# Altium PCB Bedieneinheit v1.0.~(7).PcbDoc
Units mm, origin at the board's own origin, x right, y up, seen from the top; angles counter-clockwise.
Board outline 100 x 75 mm, 2 copper layers (Top Layer, Bottom Layer); 71 components, 61 nets, 264 pads, 32 vias.
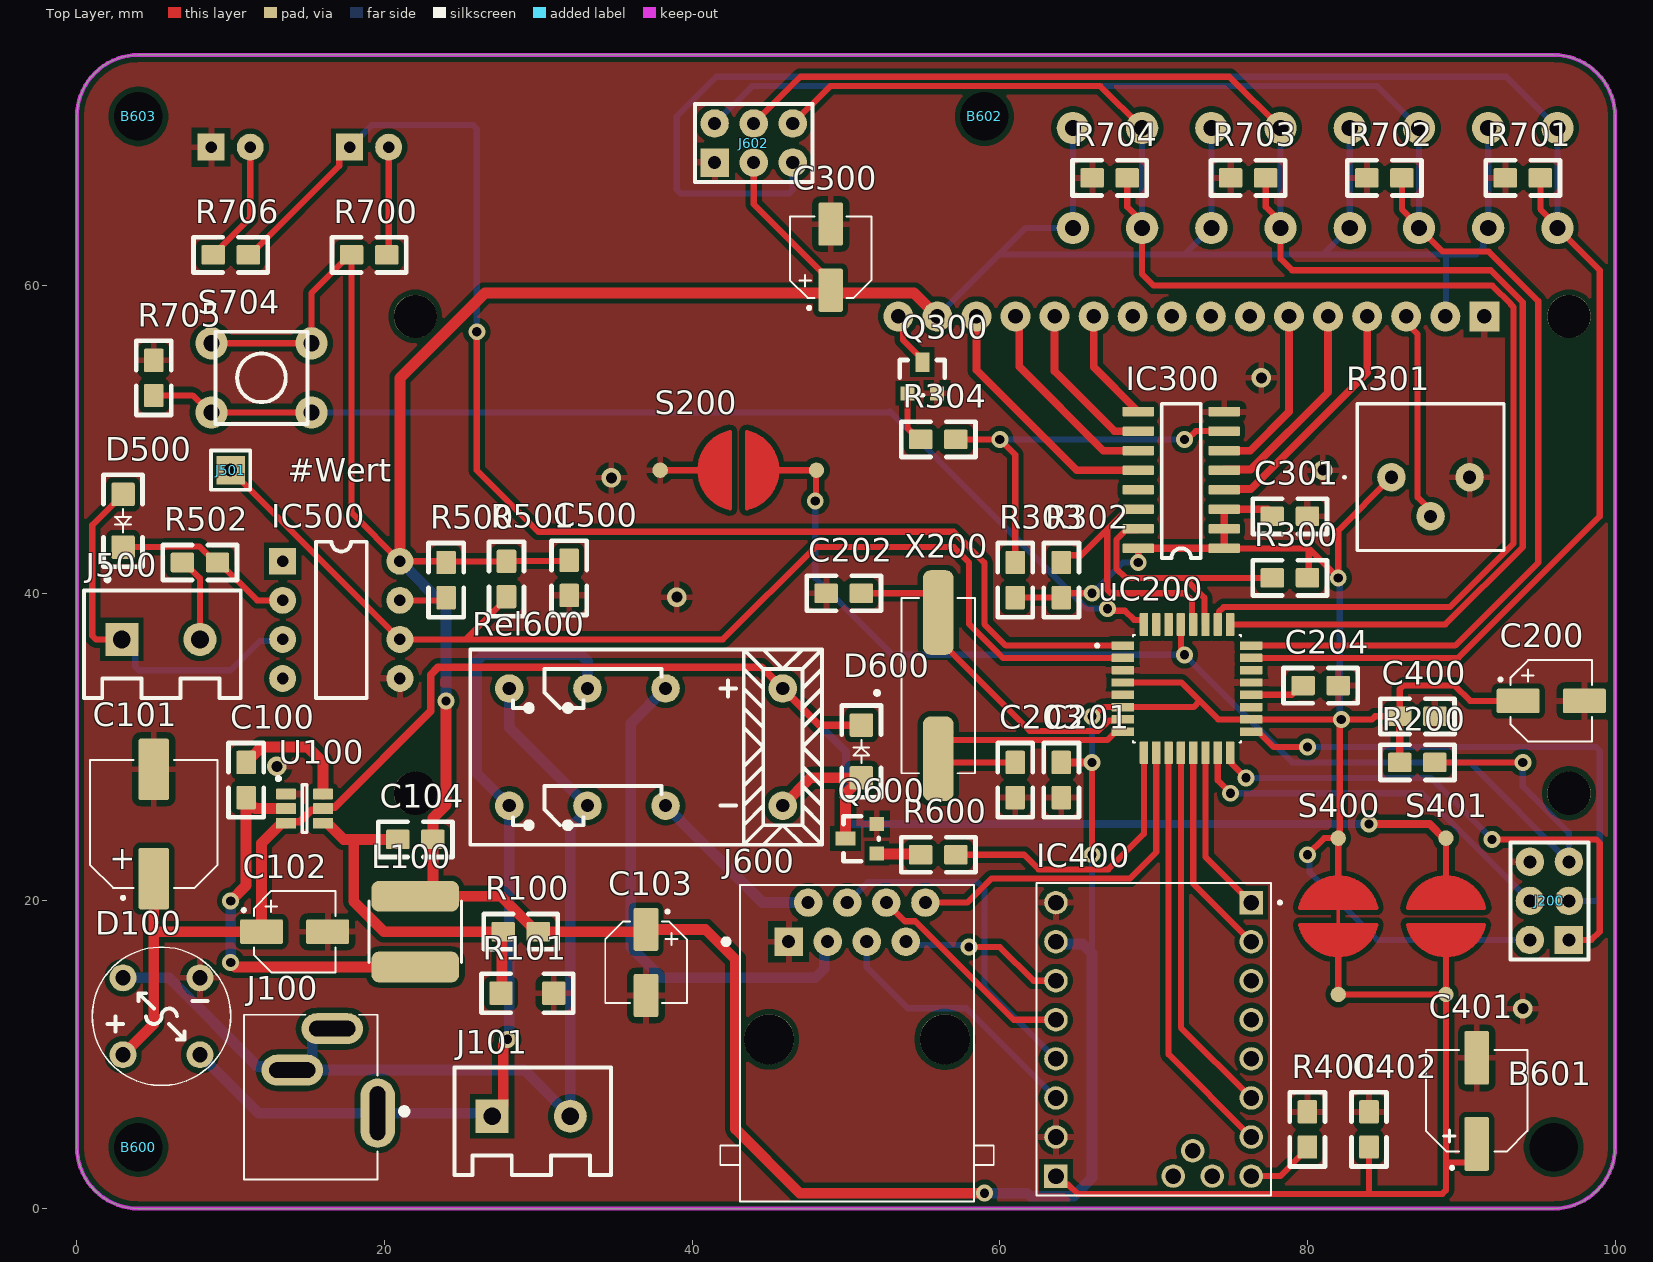
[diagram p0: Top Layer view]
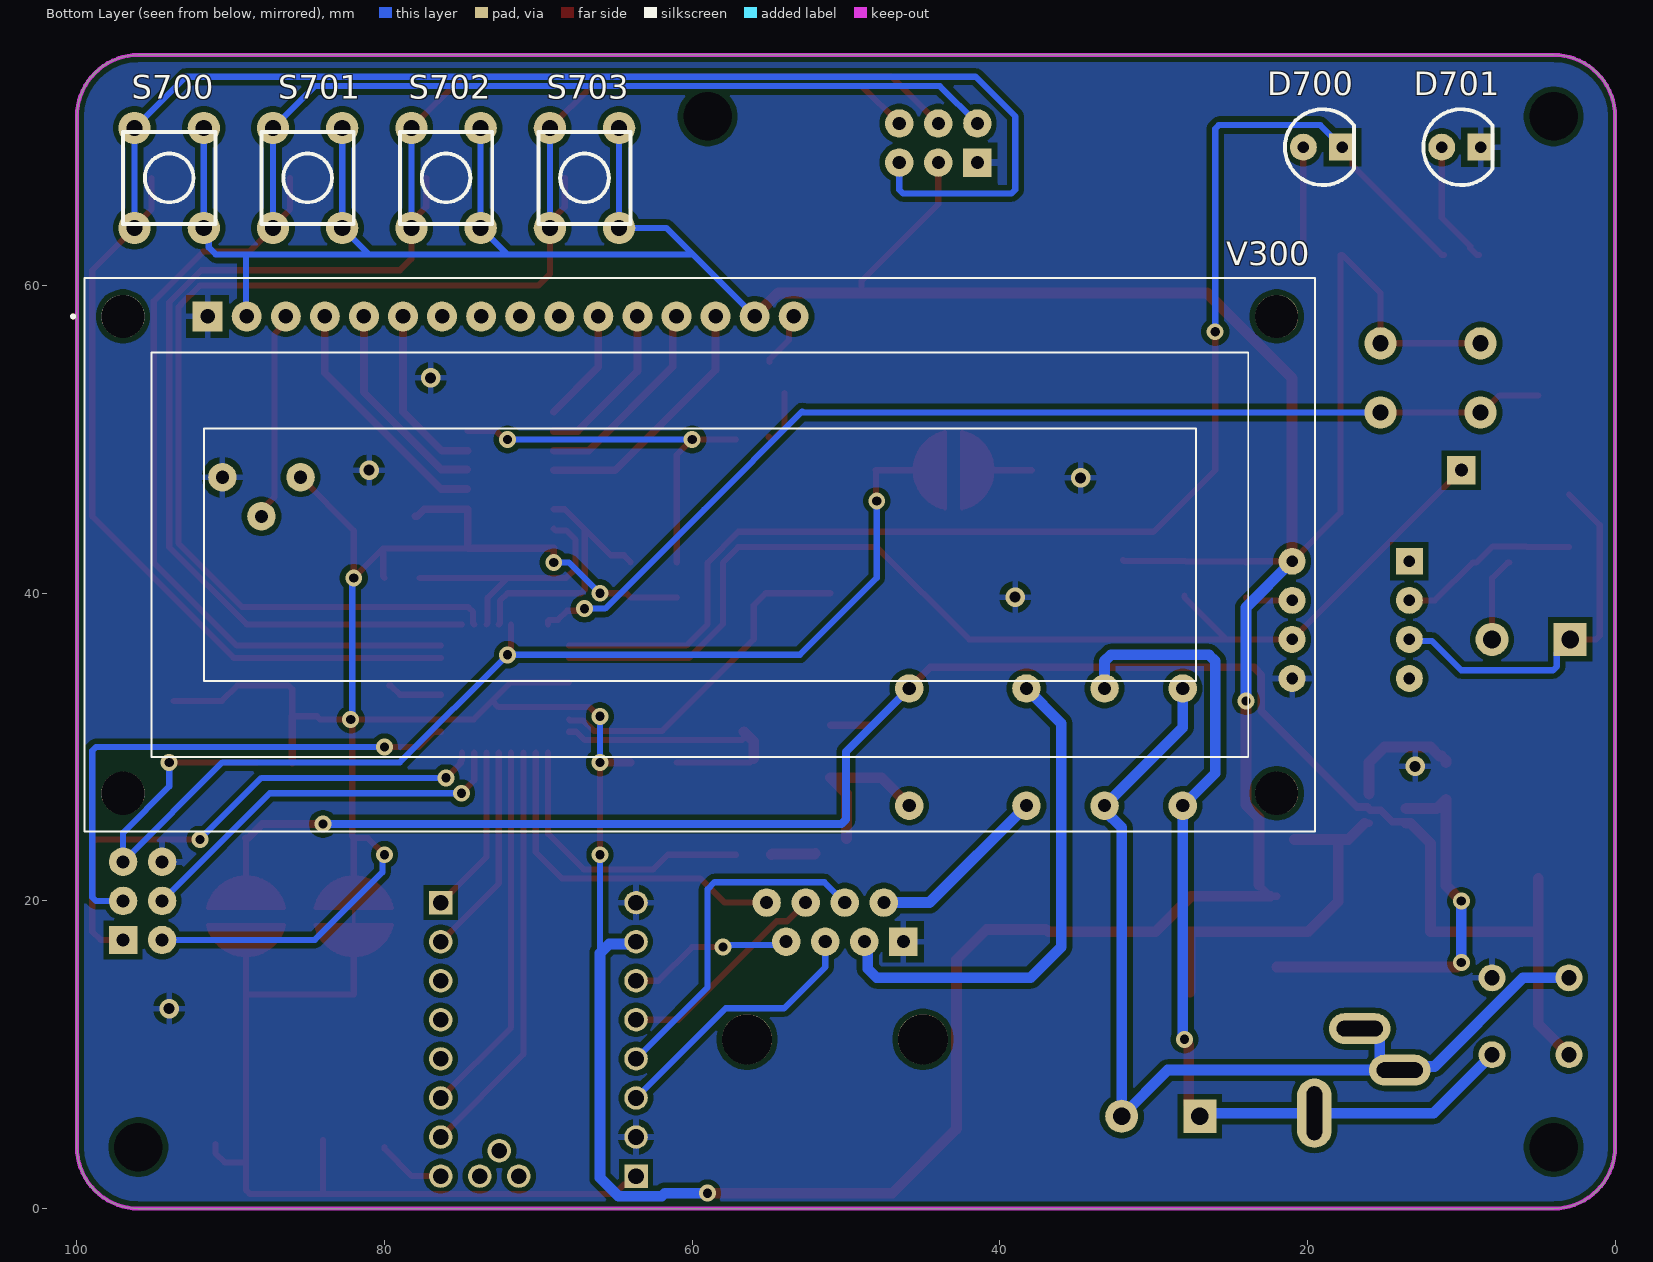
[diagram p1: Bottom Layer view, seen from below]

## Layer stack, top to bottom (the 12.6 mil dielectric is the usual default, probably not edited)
Top Solder: solder mask 0.0102, Solder Resist, Dk 3.5
Top Layer: signal copper 0.0356
Dielectric 1: dielectric 0.32, FR-4, Dk 4.8
Bottom Layer: signal copper 0.0356
Bottom Solder: solder mask 0.0102, Solder Resist, Dk 3.5

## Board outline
0,4 0,71 cw(c4,71) 4,75 96,75 cw(c96,71) 100,71 100,4 cw(c96,4) 96,0 4,0 cw(c4,4)

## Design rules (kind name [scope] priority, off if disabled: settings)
Clearance [All] p1: gap=0.35 ignorepadtopadclearanceinfootprint=FALSE except(0.2: Arc-Arc Arc-Track Arc-SMDPad Arc-THPad Arc-Via Arc-Text Arc-Hole Track-Track Track-SMDPad Track-THPad Track-Via Track-Text Track-Hole SMDPad-SMDPad SMDPad-THPad SMDPad-Via SMDPad-Text SMDPad-Hole THPad-THPad THPad-Via THPad-Text THPad-Hole Via-Via Via-Text Via-Hole Text-Text Text-Hole)
HoleSize [All] p1: absolutevalues=TRUE maxlimit=4 minlimit=0.4 maxpercent=80.000 minpercent=20.000
MinimumAnnularRing [All] p1: minimumring=0.2
MinimumSolderMaskSliver [All] p1: minsoldermaskwidth=0
PolygonConnect [All] p1: connectstyle=Relief reliefconductorwidth=0.4 reliefentries=4 polygonreliefangle="90 Angle" airgapwidth=0.4
RoutingVias [All] p1: holewidth=0.6 width=1.1 viastyle="Through Hole" minholewidth=0.5 minwidth=1 maxholewidth=1 maxwidth=2
SilkToSilkClearance [All] p1: silktosilkclearance=0
SilkToSolderMaskClearance [IsPad] p1: minsilkscreentomaskgap=0 clearancetoexposedcopper=TRUE
SolderMaskExpansion [All] p1: expansion=0.102 istentingtop=FALSE
Width [All] p1: maxlimit=6 minlimit=0.3 preferedwidth=0.5
26 further rules are at their usual default settings.

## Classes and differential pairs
component class "7.0 Bedieneinheit": D700 D701 R700 R701 R702 R703 R704 R705 R706 S700 S701 S702 S703 S704
component class "6.0 Relais and Connector": B600 B601 B602 B603 D600 J600 J602 Q600 R600 Rel600
component class "5.0 Demodulation": C500 D500 IC500 J500 J501 R500 R501 R502
component class "4.0 Steppermotor & Peripheral": C400 C401 C402 IC400 R400 S400 S401
component class "3.0 Display": C300 C301 IC300 Q300 R300 R301 R302 R303 R304 V300
component class "2.0 Microcontroller": C200 C201 C202 C203 C204 J200 R200 S200 uC200 X200
component class "1.0 PSU": C100 C101 C102 C103 C104 D100 J100 J101 L100 R100 R101 U100

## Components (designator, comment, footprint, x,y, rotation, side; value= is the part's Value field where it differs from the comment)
B600 "Schraube" B_Schraube-M3 4,4 r0 top
B601 "Schraube" B_Schraube-M3 96,4 r0 top
B602 "Schraube" B_Schraube-M3 59,71 r0 top
B603 "Schraube" B_Schraube-M3 4,71 r0 top
C100 "100nf" C_SMD_0805 11,27.857 r270 top
C101 "470uf" C_SMD_F-TYP 5,25 r90 top
C102 "10uf" C_SMD_C-TYP 14.15,18 r0 top
C103 "22uf" C_SMD_C-TYP 37,16 r270 top
C104 "22pf" C_SMD_0805 22,24 r180 top
C200 "10uf" C_SMD_C-TYP 95.85,33 r0 top
C201 "100nf" C_SMD_0805 64,27.857 r270 top
C202 "22pf" C_SMD_0805 49.857,40 r180 top
C203 "22pf" C_SMD_0805 61,27.857 r270 top
C204 "100nf" C_SMD_0805 80.857,34 r0 top
C300 "10uf" C_SMD_C-TYP 49,61.85 r90 top
C301 "100nf" C_SMD_0805 78.857,45 r0 top
C400 "100nf" C_SMD_0805 87.143,32 r0 top
C401 "100uf" C_SMD_D-TYP 91,7 r90 top
C402 "100nf" C_SMD_0805 84,5.143 r90 top
C500 "1uf" C_SMD_0805 32,41 r270 top
D100 "B500R" D_THT_FBR-R 3,10 r0 top
D500 "FDLL4148" D_SMD_1206 3,44.715 r270 top
D600 "FDLL4148" D_SMD_1206 51,29.714 r90 top
D700 "LED-YELLOW" D_THT_LED-5 19,69 r180 bottom
D701 "LED-YELLOW" D_THT_LED-5 10,69 r180 bottom
IC300 "PCF8574" SO-16 74.588,42.92 r180 top
IC400 "TMC2208" IC_TMC2208 70,11 r0 top
IC500 "6N137" DIP-8 13.38,42.08 r0 top
J100 "DC-Buchse" J_THT_CUI_PJ-006A 19.55,6.2 r270 top
J101 "VIN" "J_THT_Printklemme 2x" 29.54,6 r0 top
J200 "PROG" J_2x3 95.73,20 r90 top
J500 "DCC" "J_THT_Printklemme 2x" 5.46,37 r0 top
J501 "#Wert" SIP-1 10,49.27 r90 top
J600 "RJ45 Buchse" J_TE-RJ45-8L-B 50.715,11 r0 top
J602 "CON 2x3" J_2x3 44,69.27 r0 top
L100 "6,8uH" L_SMD_BWVS00606045 22,18 r180 top
Q300 "BC847B" SOT-23 54,53 r0 top
Q600 "BC848B" SOT-23 52,23.095 r90 top
R100 "40k2" R_SMD_0805 28.857,18 r0 top
R101 "7k68" R_SMD_1206 29.285,14 r180 top
R200 "10k" R_SMD_0805 87.143,29 r0 top
R300 "10k" R_SMD_0805 78.857,41 r0 top
R301 "10k" R_THT_POT-TP-.2/.1 85.46,47.54 r0 top
R302 "10k" R_SMD_0805 64,40.857 r270 top
R303 "10k" R_SMD_0805 61,40.857 r270 top
R304 "1k" R_SMD_0805 56,50 r180 top
R400 "0R0" R_SMD_0805 80,5.143 r270 top
R500 "10k" R_SMD_0805 24,40.857 r90 top
R501 "10k" R_SMD_0805 27.929,40.929 r90 top
R502 "1k" R_SMD_0805 8,42 r0 top
R600 "1k" R_SMD_0805 56,23 r180 top
R700 "470R" R_SMD_0805 19,62 r180 top
R701 "10k" R_SMD_0805 94,67 r0 top
R702 "10k" R_SMD_0805 85,67 r0 top
R703 "10k" R_SMD_0805 76.143,67 r0 top
R704 "10k" R_SMD_0805 67.143,67 r0 top
R705 "10k" R_SMD_0805 5,54 r270 top
R706 "470R" R_SMD_0805 10,62 r0 top
Rel600 "Nais Relais" Rel_THT_Nais 37,30 r0 top
S200 "Lötpad" S_SMD_Pad-NO#1 43,48 r0 top
S400 "Lötpad" S_SMD_Pad-NC 82,19 r90 top
S401 "Lötpad" S_SMD_Pad-NO#2 89,19 r90 top
S700 "Taster4Kl." S_THT_Taster4kl. 94,67 r90 bottom
S701 "Taster4Kl." S_THT_Taster4kl. 85,67 r90 bottom
S702 "Taster4Kl." S_THT_Taster4kl. 76,67 r90 bottom
S703 "Taster4Kl." S_THT_Taster4kl. 67,67 r90 bottom
S704 "Taster4Kl." S_THT_Taster4kl. 12,54 r180 top
U100 "DIO6970" SOT23-6 16,26.95 r0 top
uC200 "ATMega328(p)-AU" TQFP-32 72.17,33.8 r0 top
V300 "C-LCD 1602" V_MODULE_LCD-16X2 59.5,42.5 r180 bottom
X200 "16MHz" X_SMD_XTAL 56,34 r270 top

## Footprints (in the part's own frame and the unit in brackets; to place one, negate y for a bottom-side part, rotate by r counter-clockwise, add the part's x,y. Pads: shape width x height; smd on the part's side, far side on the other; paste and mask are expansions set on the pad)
B_Schraube-M3 [mm] "LB-2024-04-18"
  round 0.75 hole 3.15 unplated: 1(0,0)
C_SMD_0805 [mil] "LB-2024-04-17"
  rrect15% 60x50 smd paste-0.79 mask+1.97: 1(-45,0) 2(45,0)
  silkscreen extent -95,-45 95,45
C_SMD_C-TYP [mm] "LB-2024-04-15"
  rrect15% 2.8x1.6 smd paste-0.02 mask+0.05: 1(-2.15,0) 2(2.15,0)
  silkscreen extent -3.4,-2.65 2.65,2.65, body extent 0,0 0,0
C_SMD_D-TYP [mm] "LB-2024-04-16"
  rrect15% 3.5x1.6 smd paste-0.02 mask+0.05: 1(-2.8,0) 2(2.8,0)
  silkscreen extent -4.45,-3.3 3.3,3.3
C_SMD_F-TYP [mm] "LB-2024-04-16"
  rrect15% 4x2 smd paste-0.02 mask+0.05: 1(-3.55,0) 2(3.55,0)
  silkscreen extent -4.9,-4.15 4.15,4.15, body extent 0,0 0,0
D_SMD_1206 [mil] "LB-2024-04-17"
  rrect15% 60x60 smd paste-0.79 mask+1.97: 1(-67.5,0) 2(67.5,0)
  silkscreen extent -118,-50 155,50
D_THT_FBR-R [mm] "LB-2024-11-20"
  round 1.75 hole 1: 1(0,0) 2(5,0) 3(0,5) 4(5,5)
  silkscreen extent -2,-2 7,7
D_THT_LED-5 [mm] "LB-2024-04-17"
  round 1.75 hole 0.75: 1(-1.27,0)
  rect 1.75x1.75 hole 0.75: 2(1.27,0)
  silkscreen extent -2.47,-2.47 2.03,2.47
DIP-8 [mm] "LB-2024-04-17"
  rect 1.75x1.75 hole 0.75: 1(0,0)
  round 1.75 hole 0.75: 2(0,-2.54) 3(0,-5.08) 4(0,-7.62) 5(7.62,-7.62) 6(7.62,-5.08) 7(7.62,-2.54) 8(7.62,0)
  silkscreen extent 2.16,-8.89 5.46,1.27
IC_TMC2208 [mil] "LB-24-10-23"
  rect 60x60 hole 40: JP1_1(250,350) JP2_1(-250,-350)
  round 60 hole 40: JP1_2(250,250) JP1_3(250,150) JP1_4(250,50) JP1_5(250,-50) JP1_6(250,-150) JP1_7(250,-250) JP1_8(250,-350) JP2_2(-250,-250) JP2_3(-250,-150) JP2_4(-250,-50) JP2_5(-250,50) JP2_6(-250,150) JP2_7(-250,250) JP2_8(-250,350) JP3_1(50,-350) JP3_2(150,-350) VREF(100,-285)
  silkscreen extent -300,-400 327,400
J_2x3 [mm] "LB-2024-04-19"
  rect 1.85x1.85 hole 0.85 mask+0.102: 1(-2.54,-1.27)
  round 1.85 hole 0.85 mask+0.102: 2(-2.54,1.27) 3(0,-1.27) 4(0,1.27) 5(2.54,-1.27) 6(2.54,1.27)
  silkscreen extent -3.81,-2.54 3.81,2.54
J_TE-RJ45-8L-B [mm] "LB-2024-11-29"
  rect 1.85x1.85 hole 0.85: 1(-4.445,6.35)
  round 1.85 hole 0.85: 2(-3.175,8.89) 3(-1.905,6.35) 4(-0.635,8.89) 5(0.635,6.35) 6(1.905,8.89) 7(3.175,6.35) 8(4.445,8.89)
  round 3.25 hole 3.25 unplated: ""(-5.715,0) ""(5.715,0)
  silkscreen extent -8.89,-10.54 8.89,10.03
J_THT_CUI_PJ-006A [mm] "LB-2024-12-12"
  oval 4.5x2.25 hole 1 slot 3.5 at 0 deg: 1(0,0)
  oval 2x4 hole 1 slot 3 at 90 deg: 2(-5.5,-2.95) 3(-2.8,-5.55)
  silkscreen extent -6.4,-8.7 4.3,1.93
"J_THT_Printklemme 2x" [mm] "LB-2024-04-17"
  rect 2.15x2.15 hole 1.15: 1(-2.54,0)
  round 2.15 hole 1.15: 2(2.54,0)
  silkscreen extent -5,-3.81 5.19,3.17
L_SMD_BWVS00606045 [mm]
  rrect50% 5.7x2 smd paste-0.02 mask+0.05: 1(0,-2.3) 2(0,2.3)
  silkscreen extent -3,-2 3,2
R_SMD_0805 [mil] "LB-2024-04-17"
  rrect15% 60x50 smd paste-0.79 mask+1.97: 1(-45,0) 2(45,0)
  silkscreen extent -95,-45 95,45
R_SMD_1206 [mil] "LB-2024-04-17"
  rrect15% 60x60 smd paste-0.79 mask+1.97: 1(-67.5,0) 2(67.5,0)
  silkscreen extent -118,-50 118,50
R_THT_POT-TP-.2/.1 [mm] "LB-2024-12-11"
  round 1.85 hole 0.85: 1(0,0) 2(5.08,0) 3(2.54,-2.54)
  silkscreen extent -3.1,-4.75 7.3,4.78
Rel_THT_Nais [mm] "LB-2024-04-17"
  round 1.85 hole 0.85: 1(-8.89,-3.81) 2(-3.81,-3.81) 3(1.27,-3.81) 4(8.89,-3.81) 5(8.89,3.81) 6(1.27,3.81) 7(-3.81,3.81) 8(-8.89,3.81)
  silkscreen extent -11.43,-6.35 11.43,6.35
S_SMD_Pad-NC [mm] "LB-2024-04-18"
  round 1 smd: 1(-5.08,0) 2(5.08,0)
  Top Layer region: 0.551,2.48 0.551,-2.48 0.618,-2.413 1.016,-2.413 1.524,-1.905 1.651,-1.905 2.159,-1.397 2.159,-1.143 2.54,-0.762 2.54,0.762 2.159,1.143 2.159,1.397 1.27,2.286 1.016,2.286 0.762,2.54 0.702,2.48
  Top Layer region: -0.551,-2.48 -0.551,2.48 -0.618,2.413 -1.016,2.413 -1.524,1.905 -1.651,1.905 -2.159,1.397 -2.159,1.143 -2.54,0.762 -2.54,-0.762 -2.159,-1.143 -2.159,-1.397 -1.27,-2.286 -1.016,-2.286 -0.762,-2.54 -0.702,-2.48
  Top Layer lines w0.254: -0.762,0 -0.551,0 ; 0.762,0 0.551,0 ; -0.551,0 -0.551,-2.48 cw(c0,0) -2.54,0 cw(c0,0) -0.551,2.48 -0.551,0 ; -0.551,0 0.551,0 ; 0.551,0 0.551,-2.48 ccw(c0,0) 2.54,0 ccw(c0,0) 0.551,2.48 0.551,0
  Top Layer lines w0.4: -5.08,0 -2.54,0 -2.032,0 ; 2.032,0 2.54,0 5.08,0
S_SMD_Pad-NO#1 [mm] "LB-2024-04-18"
  round 1 smd: 1(-5.08,0) 2(5.08,0)
  Top Layer region: 0.551,2.48 0.551,-2.48 0.618,-2.413 1.016,-2.413 1.524,-1.905 1.651,-1.905 2.159,-1.397 2.159,-1.143 2.54,-0.762 2.54,0.762 2.159,1.143 2.159,1.397 1.27,2.286 1.016,2.286 0.762,2.54 0.702,2.48
  Top Layer region: -0.551,-2.48 -0.551,2.48 -0.618,2.413 -1.016,2.413 -1.524,1.905 -1.651,1.905 -2.159,1.397 -2.159,1.143 -2.54,0.762 -2.54,-0.762 -2.159,-1.143 -2.159,-1.397 -1.27,-2.286 -1.016,-2.286 -0.762,-2.54 -0.702,-2.48
  Top Layer lines w0.254: -0.551,-2.48 cw(c0,0) -0.551,2.48 -0.551,-2.48 ; 0.551,-2.48 ccw(c0,0) 0.551,2.48 0.551,-2.48
  Top Layer lines w0.4: -5.08,0 -2.032,0 ; 2.032,0 2.54,0 5.08,0
S_SMD_Pad-NO#2 [mm] "LB-2024-04-18"
  round 1 smd: 1(-5.08,0) 2(5.08,0)
  Top Layer region: 0.551,2.48 0.551,-2.48 0.618,-2.413 1.016,-2.413 1.524,-1.905 1.651,-1.905 2.159,-1.397 2.159,-1.143 2.54,-0.762 2.54,0.762 2.159,1.143 2.159,1.397 1.27,2.286 1.016,2.286 0.762,2.54 0.702,2.48
  Top Layer region: -0.551,-2.48 -0.551,2.48 -0.618,2.413 -1.016,2.413 -1.524,1.905 -1.651,1.905 -2.159,1.397 -2.159,1.143 -2.54,0.762 -2.54,-0.762 -2.159,-1.143 -2.159,-1.397 -1.27,-2.286 -1.016,-2.286 -0.762,-2.54 -0.702,-2.48
  Top Layer lines w0.254: -0.551,2.48 ccw(c0,0) -2.54,0 ccw(c0,0) -0.551,-2.48 -0.551,2.48 ; 0.551,2.48 cw(c0,0) 2.54,0 cw(c0,0) 0.551,-2.48 0.551,2.48
  Top Layer lines w0.4: -5.08,0 -2.54,0 -2.032,0 ; 2.032,0 2.54,0 5.08,0
S_THT_Taster4kl. [mm] "LB-2024-04-17"
  round 2.1 hole 1.05: 1(-3.25,2.25) 1(3.25,2.25) 2(-3.25,-2.25) 2(3.25,-2.25)
  silkscreen extent -3,-3 3,3
SIP-1 [mm] "LB-2024-04-17"
  rect 1.85x1.85 hole 0.85: 1(-1.27,0)
  silkscreen extent -2.54,-1.27 0,1.27
SO-16 [mil] "LB-2024-04-17"
  rrect15% 80x24 smd paste-0.79 mask+1.97: 1(0,0) 2(0,-50) 3(0,-100) 4(0,-150) 5(0,-200) 6(0,-250) 7(0,-300) 8(0,-350) 9(220,-350) 10(220,-300) 11(220,-250) 12(220,-200) 13(220,-150) 14(220,-100) 15(220,-50) 16(220,0)
  silkscreen extent 60,-370 160,25
SOT23-6 [mm] "LB-2024-04-25"
  rrect15% 1.3x0.7 smd paste-0.02 mask+0.05: 1(-2.4,0) 2(-2.4,-0.95) 3(-2.4,-1.9) 4(0,-1.9) 5(0,-0.95) 6(0,0)
  silkscreen extent -3,-2.5 -1.05,1.1
SOT-23 [mil]
  rect 36x36 smd: 1(0,0) 2(75,0)
  rect 36x50 smd: 3(38,80)
  silkscreen extent -20,-5 95,85
TQFP-32 [mm] "LB-2024-04-19"
  rrect15% 1.47x0.55 smd paste-0.02 mask+0.05: 1(-4.17,2.8) 2(-4.17,2) 3(-4.17,1.2) 4(-4.17,0.4) 5(-4.17,-0.4) 6(-4.17,-1.2) 7(-4.17,-2) 8(-4.17,-2.8) 17(4.17,-2.8) 18(4.17,-2) 19(4.17,-1.2) 20(4.17,-0.4) 21(4.17,0.4) 22(4.17,1.2) 23(4.17,2) 24(4.17,2.8)
  rrect15% 0.55x1.47 smd paste-0.02 mask+0.05: 9(-2.8,-4.17) 10(-2,-4.17) 11(-1.2,-4.17) 12(-0.4,-4.17) 13(0.4,-4.17) 14(1.2,-4.17) 15(2,-4.17) 16(2.8,-4.17) 25(2.8,4.17) 26(2,4.17) 27(1.2,4.17) 28(0.4,4.17) 29(-0.4,4.17) 30(-1.2,4.17) 31(-2,4.17) 32(-2.8,4.17)
  silkscreen extent -5.94,-3.5 3.5,3.5
V_MODULE_LCD-16X2 [mm] "LB-2024-11-29"
  rect 1.95x1.95 hole 0.95: 1(-32,15.5)
  round 1.95 hole 0.95: 2(-29.46,15.5) 3(-26.92,15.5) 4(-24.38,15.5) 5(-21.84,15.5) 6(-19.3,15.5) 7(-16.76,15.5) 8(-14.22,15.5) 9(-11.68,15.5) 10(-9.14,15.5) 11(-6.6,15.5) 12(-4.06,15.5) 13(-1.52,15.5) 14(1.02,15.5) 15(3.56,15.5) 16(6.1,15.5)
  round 2.8 hole 2.8 unplated: ""(-37.5,-15.5) ""(-37.5,15.5) ""(37.5,-15.5) ""(37.5,15.5)
  silkscreen extent -40.85,-18 40,18
X_SMD_XTAL [mm] "LB-2024-04-17"
  rrect50% 5.5x2 smd paste-0.02 mask+0.05: 1(-4.75,0) 2(4.75,0)
  silkscreen extent -5.7,-2.4 5.7,2.4

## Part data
B600 B601 B602 B603: library part B_Schraube, "Schraubenloch für M3 Schrauben"
C100 C104 C201 C202 C203 C204 C301 C400 C402 C500: library part C_SMD_KO, "Kondensator SMD Universal, Keramik, Folie, usw."
C101 C102 C103 C200 C300 C401: library part C_SMD_ELK, "SMD Elektrolytkondensator"
D100: library part D_THT_Brückengleichrichter, "Bruckengleichrichter"
D500 D600: library part D_SMD_Silizium, "Diode SMD Silizium"
D700 D701: library part D_THT_LED, "Diode THT LED"
IC300: library part IC_PCF8574, "I/O Expander"
IC400: library part IC_TMC2208, "Schrittmotortreiber"
IC500: library part IC_6N137, "Optokoppler"
J100: library part J_THT_Hohlstecker
J101 J500: library part "J_THT_Printklemme 2x", "Printklemme"
J200 J602: library part "J_THT_IDC 2x3", "Stecker"
J501: library part J_THT_CON1, "Stecker"
J600: library part J_RJ45, "Connector"
L100: library part L_SMD_Spule, "Spule SMD"
Q300 Q600: library part Q_SMD_NPN, "NPN Transistor"
R100 R101 R200 R300 R302 R303 R304 R400 R500 R501 R502 R600 R700 R701 R702 R703 R704 R705 R706: library part R_SMD_Widerstand, "Widerstand SMD"
R301: library part R_THT_Potentiometer, "Potentiometer"
Rel600: library part Rel_THT_Nais, "Nais DS2Y-S-DC12V"
S200 S400 S401: library part S_SMD_Jumper, "Lötverbinder"
S700 S701 S702 S703 S704: library part S_THT_Taster, "Taster"
U100: library part U_DIO6970, "Buckconverter"
uC200: library part UC_ATMega328P-AU, "Microcontroller"
V300: library part V_C-LCD-1602, "LC-Display", Package=None
X200: library part X_SMD_Quarz, "Quarz SMD"

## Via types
v1: diameter 1.1, hole 0.6, Top Layer to Bottom Layer, 26 vias
v2: diameter 1.27, hole 0.711, Top Layer to Bottom Layer, 6 vias

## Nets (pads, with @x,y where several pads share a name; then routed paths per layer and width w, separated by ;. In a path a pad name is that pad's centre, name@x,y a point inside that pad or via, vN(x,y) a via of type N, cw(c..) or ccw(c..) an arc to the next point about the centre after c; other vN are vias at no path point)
+5V: C103.1 C104.1 C200.1 C201.1 C300.1 C301.1 C400.1 C500.1 IC300.1 IC300.2 IC300.3 IC300.16 IC400.JP2_7 IC500.8 J200.2 J602.3 L100.1 R100.2 R200.1 R300.2 R301.1 R302.2 R303.2 R500.2 R501.2 R700.2 S400.2 S700.2 S701.2 S702.2 S703.2 S704.2 uC200.4 uC200.6 uC200.18 V300.2 V300.15 | length 418.8
  Top Layer w0.4: S704.2@8.75,56.25 15.25,56.25 15.25,59.52 17.73,62 R700.2 17.857,45.223 IC500.8 23.92,42.08 R500.2 24.072,42.072 R501.2 27.964,42.107 31.964,42.107 C500.1 ; J602.3 44,65.3 49,60.3 C300.1 ; R303.2 R302.2 64.286,40 v1(66,40) ; v1(66,23) v1(66,29) ; v1(66,32) 66.065,32 66.665,32.6 uC200.6 72.6,32.6 73,33 ; uC200.4 71.8,34.2 73,33 ; v1(69,42) IC300.16 ; IC300.1 80.08,42.92 ; v1@80,23.189 v1(80,23) 81.08,24.08 S400.2 82.1,24.18 82.1,31.7 v1(82.2,31.8) ; R300.2 80.08,41.08 80.08,42.92 ; R301.1 82,44.08 v1(82,41) 80.08,42.92 ; C200.1 90.584,33 89.584,34 86.234,34 86,33.766 C400.1 84.4,32 84.2,31.8 v1(82.2,31.8) ; 73,33 74.2,31.8 uC200.18 v1(82.2,31.8)
  Top Layer w0.5: L100.1 22.412,20.3 L100.1@23.143,21.031 ; R100.2@29.873,18 R100.2 ; C103.1@36.85,18 C103.1 ; C201.1 v1(66,29) ; IC300.16 IC300.1 IC300.2 IC300.3 77.413,45.46 77.873,45 C301.1@78,45 ; R200.1 C400.1
  Top Layer w0.7: IC500.8 21,54 26.525,59.525 54.415,59.525 V300.15 ; L100.1@22.412,20.3 27.573,20.3 R100.2@29.873,18 ; L100.1@23.143,21.031 C104.1 23.143,25.385 24,26.242 v1(24,33) ; R100.2 C103.1@36.85,18 ; C103.1 40.85,18.15 42.825,16.175 42.825,5.175 47,1 v1(59,1)
  Bottom Layer w0.4: V300.15 59.97,62.03 ; S703.2@64.75,70.25 64.75,63.75 61.69,63.75 59.97,62.03 ; 66,16.59 v1(66,23) ; v1(66,29) v1(66,32) ; v1(66,40) 68,42 v1(69,42) ; S702.2@73.75,70.25 73.75,63.75 72.03,62.03 ; v1(80,23) 80.134,22.866 80.134,21.866 84.54,17.46 J200.2 ; v1(82,41) 82.1,40.9 82.1,31.9 v1(82.2,31.8) ; S701.2@82.75,70.25 82.75,63.75 81.03,62.03 ; V300.2 89,58.04 89,62.03 ; S700.2@91.75,70.25 91.75,63.75 91.425,63.425 91.425,62.485 90.97,62.03 89,62.03 ; 59.97,62.03 72.03,62.03 ; 72.03,62.03 81.03,62.03 ; 81.03,62.03 89,62.03
  Bottom Layer w0.7: IC500.8 24,39.08 v1(24,33) ; v1(59,1) 61.773,1 61.975,0.798 64.798,0.798 66,2 66,16.59 65.398,17.192 63.808,17.192 IC400.JP2_7
ADC6: uC200.19
ADC7: uC200.22
BL: IC300.7 R303.1 R304.1 | length 26.1
  Top Layer w0.4: R304.1 v1(60,50) 61,49 R303.1 ; v1(72,50) 72.189,50 72.729,50.54 IC300.7
  Bottom Layer w0.4: v1(60,50) v1(72,50)
D4: IC300.9 V300.11 | length 7.4
  Top Layer w0.5: V300.11 66.1,54.71 IC300.9
D5: IC300.10 V300.12 | length 10.6
  Top Layer w0.5: V300.12 63.56,54.44 67.46,50.54 IC300.10
D6: IC300.11 V300.13 | length 13.4
  Top Layer w0.5: V300.13@61.259,57.761 61.259,54.741 66.73,49.27 IC300.11
  Top Layer w0.7: V300.13 V300.13@61.259,57.761
D7: IC300.12 V300.14 | length 16.7
  Top Layer w0.5: V300.14 58.48,54.52 65,48 IC300.12
DCC: IC500.6 J501.1 R501.1 uC200.2 | length 74.4
  Top Layer w0.4: J501.1 IC500.6 25.27,37 ; R501.1@28,39.857 28,39.73 25.27,37 ; uC200.2 60.2,35.8 58,38 58,42 57,43 48,43 42,37 25.27,37
EN: IC300.6 V300.6 | length 11.5
  Top Layer w0.5: IC300.6 76.27,49.27 78.8,51.8 V300.6
ESS: J600.8 uC200.10 | length 22.8
  Top Layer w0.4: J600.8 57.89,19.89 59.45,21.45 68.45,21.45 70.17,23.17 uC200.10
FRST: R705.2 S704.1 uC200.32 | length 70.7
  Top Layer w0.4: R705.2 7.524,52.857 8.631,51.75 8.75,51.75 S704.1@15.25,51.75 ; v1(67,39) 67.134,38.866 68.134,38.866 68.729,38.271 69.295,38.271 69.37,38.196 uC200.32
  Bottom Layer w0.4: S704.1@15.25,51.75 52.766,51.75 52.842,51.826 59.224,45.444 59.224,45.432 65.656,39 v1(67,39)
GND: C101.2 C102.2 C103.2 C200.2 C201.2 C202.2 C203.2 C204.2 C300.2 C301.2 C400.2 C401.2 C402.2 C500.2 D100.4 D701.2 IC300.8 IC400.JP2_2 IC400.JP2_8 IC500.5 J200.6 J600.1 J602.1 Q300.2 Q600.2 R101.1 R301.2 R400.1 R701.1 R702.1 R703.1 R704.1 R705.1 S200.1 U100.1 uC200.3 uC200.5 uC200.21 V300.1
  other v2: 94,13 13,28.75 39,39.75 34.75,47.5 81,48 77,54
GND-Diff: J600.2 Rel600.3 | length 11.9
  Bottom Layer w0.7: Rel600.3 44.57,19.89 J600.2
LED: D700.2 R706.2 uC200.1 | length 90
  Top Layer w0.4: R706.2 11.27,62 17.055,67.785 17.055,68.325 D700.2 ; v1(26,57) 26,48 30,44 57,44 59,42 59,38 60.4,36.6 uC200.1
  Bottom Layer w0.4: D700.2 19.164,70.434 25.766,70.434 26,70.2 v1(26,57)
M1: IC400.JP2_4 J600.4 | length 22.6
  Bottom Layer w0.4: J600.4 51.405,21.215 58.551,21.215 59,20.766 59,14.38 IC400.JP2_4
M2: IC400.JP2_3 J600.5 | length 17.5
  Bottom Layer w0.4: J600.5 51.35,15.7 54.025,13.025 57.815,13.025 IC400.JP2_3
M3: IC400.JP2_5 J600.6 | length 14.2
  Top Layer w0.4: J600.6 53.835,18.675 54.501,18.675 60.906,12.27 IC400.JP2_5
M4: IC400.JP2_6 J600.7 | length 10.8
  Top Layer w0.4: v1(58,17) 60,17 62.19,14.81 IC400.JP2_6
  Bottom Layer w0.4: J600.7 54.106,17.134 57.866,17.134 v1(58,17)
MISO: J200.1 uC200.16 | length 34.8
  Top Layer w0.4: uC200.16 74.97,29.17 75.045,29.095 75.045,28.956 75.14,28.861 ; 75.14,28.86 v1(76,28) ; v1(92,24) 98.766,24 99,23.766 99,18 98.46,17.46 J200.1
  Bottom Layer w0.4: v1(76,28) 88,28 v1(92,24)
MOSI: J200.4 uC200.15 | length 25.3
  Top Layer w0.4: uC200.15 74.17,27.83 v1(75,27)
  Bottom Layer w0.4: v1(75,27) 87.46,27 J200.4
MS1: IC400.JP1_7 uC200.11 | length 27.2
  Top Layer w0.4: uC200.11 70.97,10.03 IC400.JP1_7
MS2: IC400.JP1_6 uC200.12 | length 24.3
  Top Layer w0.4: uC200.12 71.77,11.77 IC400.JP1_6
NetC100_1: C100.1 U100.6 | length 8
  Top Layer w0.7: C100.1 11,29.127 11.285,29.412 11.412,29.412 12,30 15,30 16,29 U100.6
NetC100_2: C100.2 L100.2 U100.2 | length 26.1
  Top Layer w0.5: v1(10,16) v1@10.3,15.7 ; C100.2@11,26.587 C100.2
  Top Layer w0.7: v1(10,20) 11,21 11,26.587 11.587,26 U100.2 ; v1@10.3,15.7 L100.2
  Bottom Layer w0.7: v1(10,16) v1(10,20)
NetC104_2: C104.2 R100.1 R101.2 U100.4 | length 23.9
  Top Layer w0.5: U100.4 U100.4@16.3,25.05 ; R101.2 R101.2@27.642,14.072 ; R100.1@27.642,17.928 R100.1
  Top Layer w0.7: U100.4@16.3,25.05 17.35,24 18,24 ; C104.2 18,24 ; R101.2@27.642,14.072 R100.1@27.642,17.928 ; R100.1 19.965,18 18,19.965 18,24
NetC202_1: C202.1 uC200.7 X200.1 | length 22.3
  Top Layer w0.4: C202.1 55.223,40 56,39.223 X200.1 56,37 61.95,31.05 66.394,31.05 67.069,31.725 67.925,31.725 uC200.7
NetC203_1: C203.1 uC200.8 X200.2 | length 19.2
  Top Layer w0.4: X200.2 56.25,29 C203.1 ; X200.2@56.639,31 56.639,30.589 56.777,30.45 66.99,30.45 67.54,31 uC200.8
  Top Layer w0.7: X200.2 56,30.361 X200.2@56.639,31
NetC204_1: C204.1 uC200.20 | length 3.6
  Top Layer w0.4: uC200.20 78.987,33.4 79.587,34 C204.1
NetC401_1: C401.1 C402.1 IC400.JP2_1 S400.1 S401.1 | length 52
  Top Layer w0.4: IC400.JP2_1 64.212,1.548 64.452,1.548 65.052,0.948 84,0.948 ; S400.1 S401.1 89,3 ; C402.1@84,4.453 C402.1 84,0.948 ; C401.1 91,3.6 90.4,3 89,3 ; 84,0.948 88.766,0.948 89,1.182 89,3
NetD500_1: D500.1 IC500.3 J500.1 | length 24.7
  Top Layer w0.4: J500.1 1.234,37 1,37.234 1,44.429 D500.1
  Bottom Layer w0.4: J500.1 3.795,36.125 3.795,35.234 4.029,35 10,35 11.905,36.905 13.285,36.905 IC500.3
NetD500_2: D500.2 IC500.2 R502.2 | length 11.8
  Top Layer w0.4: D500.2 5.754,43 5.789,43.035 7.981,43.035 9.016,42 R502.2 9.27,42 11.73,39.54 IC500.2
NetD600_1: D600.1 Q600.3 Rel600.4 | length 10.2
  Top Layer w0.7: Rel600.4 47.7,28 D600.1 49.968,26.968 Q600.3
NetD700_1: D700.1 R700.1 | length 7.1
  Top Layer w0.4: R700.1 20.27,62.127 D700.1
NetD701_1: D701.1 R706.1 | length 8.1
  Top Layer w0.4: R706.1 8.984,62 9.419,62.435 9.419,62.562 11.27,64.413 D701.1
NetIC400_JP1_8: IC400.JP1_8 R400.2 | length 4.6
  Top Layer w0.4: IC400.JP1_8 78.237,2.11 80,3.873 R400.2
  Bottom Layer w0.4: IC400.JP1_8 IC400.JP1_8@76.405,2.055
NetIC500_7: IC500.7 R500.1 | length 3.1
  Top Layer w0.4: IC500.7 23.826,39.54 R500.1
NetJ500_2: J500.2 R502.1 | length 5.5
  Top Layer w0.4: R502.1 6.984,42 8,40.984 J500.2
NetQ300_1: Q300.1 R304.2 | length 3.7
  Top Layer w0.4: Q300.1 54,50.73 54.73,50 R304.2 R304.2@55.035,50.178
NetQ300_3: Q300.3 V300.16 | length 3.6
  Top Layer w0.4: V300.16 53.697,57.703 53.697,56.478 54.965,55.21 Q300.3
NetQ600_1: Q600.1 R600.2 | length 2.9
  Top Layer w0.7: Q600.1 52.048,23.048 54.809,23.048 R600.2
NetR301_3: R301.3 V300.3 | length 13.7
  Top Layer w0.4: V300.3 86.42,57.581 87.157,56.844 87.157,46.235 88,45.392 R301.3
RS: IC300.4 V300.4 | length 16
  Top Layer w0.5: IC300.4@74.633,46.775 76.321,46.775 83.88,54.334 V300.4
RST: J200.5 R200.2 S200.2 uC200.29 | length 79.2
  Top Layer w0.4: v1(48,46) 48.04,46.04 48.04,47.96 S200.2 ; uC200.29 71.77,36.419 72,36.189 v1(72,36) ; R200.2 v1(94,29)
  Bottom Layer w0.4: v1(48,46) 48,41 53,36 v1(72,36) 79,29 90.54,29 J200.5 97,24.439 94,27.439 v1(94,29)
RW: IC300.5 V300.5 | length 13.7
  Top Layer w0.5: IC300.5@74.633,48.045 76.318,48.045 81.34,53.067 V300.5
RX: uC200.30
S-DIR: IC400.JP1_1 uC200.14 | length 11
  Top Layer w0.4: uC200.14 73.37,22.87 IC400.JP1_1
S-STEP: IC400.JP1_2 uC200.13 | length 13.8
  Top Layer w0.4: uC200.13 72.57,21.13 IC400.JP1_2
SCK: J200.3 uC200.17 | length 34.8
  Top Layer w0.4: uC200.17 76.8,31 77.8,30 v1(80,30)
  Bottom Layer w0.4: v1(80,30) 98.766,30 99,29.766 99,20.234 98.766,20 J200.3
SCL: IC300.14 R302.1 uC200.28 | length 17.8
  Top Layer w0.4: R302.1 64,42.032 64.435,42.467 65.296,42.467 67,44.171 ; IC300.14 68.289,45.46 67,44.171 ; uC200.28 72.495,38.045 72.495,39.505 72,40 67.218,40 66.984,40.234 66.984,43.612 67,43.628 67,44.171
SDA: IC300.15 R300.1 uC200.27 | length 17.6
  Top Layer w0.4: IC300.15 68.895,44.085 68.184,44.085 67.584,43.485 67.584,41.608 68.192,41 72,41 ; uC200.27 73.295,38.045 73.295,39.705 72,41 ; R300.1 72,41
T-180: J602.4 R703.2 S702.1 uC200.25 | length 103
  Top Layer w0.4: J602.4 47.035,73.575 74.925,73.575 S702.1@78.25,70.25 ; uC200.25 88.97,37.97 94,43 94,58.917 91.917,61 79,61 78.25,61.75 78.25,63.75 78.25,64.155 77.286,65.119 R703.2
  Bottom Layer w0.4: S702.1@78.25,63.75 S702.1@78.25,70.25
T-+: J602.5 R701.2 S700.1 uC200.23 | length 130.5
  Top Layer w0.4: uC200.23 89.8,35.8 99,45 99,61 96.25,63.75 96.25,63.869 95.143,64.976 R701.2
  Bottom Layer w0.4: J602.5 46.54,66.234 46.306,66 39.234,66 39,66.234 39,71 41.575,73.575 92.925,73.575 96.25,70.25 S700.1@96.25,63.75
T--: J602.2 R702.2 S701.1 uC200.24 | length 105.8
  Top Layer w0.4: uC200.24 89.6,36.6 95,42 95,59 91.788,62.212 88.788,62.212 87.25,63.75 87.25,63.869 86.143,64.976 R702.2
  Bottom Layer w0.4: J602.2 43.895,72.975 84.525,72.975 87.25,70.25 S701.1@87.25,63.75
T-Play: J602.6 R704.2 S703.1 uC200.26 | length 100.3
  Top Layer w0.4: J602.6 48.975,72.975 66.525,72.975 S703.1@69.25,70.25 ; R704.2 68.286,65.119 69.25,64.155 69.25,63.75 69.25,60.75 70,60 92.016,60 93.241,58.775 93.241,58.759 93.4,58.6 93.4,43.249 89.256,39.105 74.553,39.105 74.245,38.797 74.245,38.045 uC200.26
  Bottom Layer w0.4: S703.1@69.25,63.75 S703.1@69.25,70.25
TX: uC200.31
VCC: C101.1 C102.1 D100.1 D600.2 Rel600.5 S401.2 U100.3 U100.5 | length 121.4
  Top Layer w0.5: U100.3 13.7,25.15 14.494,25.15 15.244,25.9 15.9,25.9 U100.5 16.1,26.1 16.756,26.1 23,32.344 23,34.707 23.478,35.185 44.515,35.185 Rel600.5 48.271,31.429 D600.2 ; v1(84,25) 87.945,25 88.865,24.08 S401.2
  Top Layer w0.7: D100.1 5,12 5,18 ; C101.1 5,18 ; U100.3 13.3,25.05 12,23.75 C102.1 5,18
  Bottom Layer w0.5: Rel600.5 50,29.7 50,25.293 50.293,25 v1(84,25)
VCC-Diff: J600.3 Rel600.6 | length 33.3
  Bottom Layer w0.7: Rel600.6 36,31.54 36,17 38,15 48,15 48.59,15.59 48.59,17.13 J600.3
VSSW: R600.1 uC200.9 | length 18.8
  Top Layer w0.4: R600.1 61.574,23 62.524,22.05 67.05,22.05 69.37,24.37 uC200.9
VW1: D100.3 J100.2 J100.3 J101.2 Rel600.2 Rel600.8 | length 66
  Bottom Layer w0.381: J100.2@15.3,10.952 16.048,11.7 J100.2
  Bottom Layer w0.7: D100.3 5.985,15 11.743,9.242 13.758,9.242 J100.3 29.08,9 J101.2 32.08,24.769 33.19,25.879 Rel600.2 28.11,31.27 Rel600.8 ; J100.3@15.3,9.748 J100.2@15.3,10.952
VW2: D100.2 J100.1 J101.1 Rel600.1 Rel600.7 | length 60.9
  Top Layer w0.7: J101.1 27.725,6.725 27.725,10.617 28,10.892 v1(28,11)
  Bottom Layer w0.381: J101.1@26.8,6.2 J101.1
  Bottom Layer w0.7: D100.2 11.8,6.2 J100.1 J101.1@26.8,6.2 ; v1(28,11) 28.11,11.11 Rel600.1 26,28.3 26,35.59 26.41,36 32.78,36 33.19,35.59 Rel600.7
pads on no net: B600.1 B601.1 B602.1 B603.1 IC300.13 IC400.JP1_3 IC400.JP1_4 IC400.JP1_5 IC400.JP3_1 IC400.JP3_2 IC400.VREF IC500.1 IC500.4 J600. V300. V300.7 V300.8 V300.9 V300.10

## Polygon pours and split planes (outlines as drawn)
GND on Bottom Layer "GND_L02_P001" (solid, remove dead copper, pour order 1): -12,80 -9,77 106,77 106,-4 100,-10 99,-9 -7,-9 -7,76 -11,80
GND on Top Layer "GND_L01_P000" (solid, remove dead copper, pour order 0): -3,83 -2,82 108,82 108,-5 104,-9 -4,-9 -4,77 -3,78

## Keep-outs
Keep-Out Layer:
  the board outline again, w0.254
